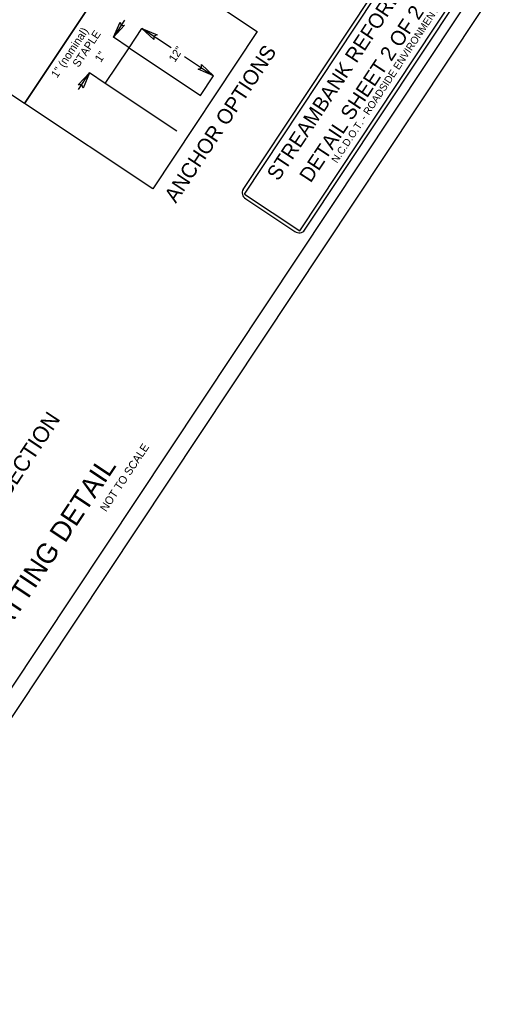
# Model space of a CAD drawing. Extents: x 561231 to 564240, y 590260 to 602519.
# Drawn here: x 563838 to 564240, y 590260 to 591058 of the extents above; entities that cross this region are included whole.
import ezdxf

# ---------------------------------------------------------------- set-up
doc = ezdxf.new("R2010")
doc.units = 0
doc.layers.add('Old_Level_1', color=7, linetype='Continuous')
doc.layers.add('Sheet Plot Border Outside CELL', color=7, linetype='Continuous')

msp = doc.modelspace()

# ---------------------------------------------------------------- linework, layer by layer
at = {"layer": 'Old_Level_1'}
for p, q in [((564021.45, 590918.69), (564158.67, 591125.58)), ((564022.5, 590914.8), (564162.65, 591126.13)), ((564067.77, 590884.76), (564207.92, 591096.09)), ((564071.76, 590885.31), (564208.97, 591092.21)), ((563924.5, 591057.12), (563915.26, 591043.22)), ((563928.1, 591034.49), (563938.64, 591050.47)), ((563936.85, 591047.77), (563936.82, 591047.73)), ((563962.45, 591034.64), (563938.64, 591050.46)), ((563912.53, 591045.03), (563912.53, 591045.03)), ((563928.1, 591034.49), (563915.26, 591043.22)), ((563973.37, 591027.38), (563997.18, 591011.56)), ((563886.76, 591000.32), (563895.82, 591013.96)), ((563908.64, 591005.23), (563895.81, 591013.97)), ((563898.54, 591012.16), (563898.55, 591012.15)), ((563986.62, 590995.57), (563997.18, 591011.56)), ((563995.37, 591008.83), (563995.37, 591008.83)), ((564022.5, 590914.8), (564067.77, 590884.76)), ((564023.55, 590910.92), (564063.79, 590884.22))]:
    msp.add_line(p, q, dxfattribs=at)
for points in [[(563698.59, 591448.69), (563200.53, 590699.06), (563725.27, 590350.42), (564223.33, 591100.04)], [(563700.37, 591083.36), (563785.96, 591212.17), (563928.11, 591117.72), (563842.52, 590988.91)], [(563842.52, 590988.91), (563928.11, 591117.72), (564033.01, 591048.02), (563947.43, 590919.21)], [(563924.5, 591053.01), (563915.26, 591043.22), (563920.69, 591055.64), (563921.71, 591052.92)], [(563948.42, 591041.22), (563938.64, 591050.46), (563951.06, 591045.04), (563948.33, 591044.02)], [(563886.58, 591004.17), (563895.82, 591013.96), (563890.41, 591001.55), (563889.38, 591004.26)], [(563987.39, 591020.8), (563997.18, 591011.56), (563984.76, 591016.98), (563987.48, 591018)]]:
    msp.add_lwpolyline(points, close=True, dxfattribs=at)
msp.add_lwpolyline([(563967.17, 590966.32), (563908.64, 591005.23), (563928.1, 591034.49), (563986.62, 590995.57)], dxfattribs=at)
for centre, major_axis, start_param, end_param in [((564026.48, 590915.35), (-5.03, 3.34), 0.000749, 1.571546), ((564066.73, 590888.65), (5.03, -3.34), 4.713138, 6.283935)]:
    msp.add_ellipse(centre, major_axis=major_axis, ratio=0.880425, start_param=start_param, end_param=end_param, dxfattribs=at)
at = {"layer": 'Sheet Plot Border Outside CELL'}
msp.add_lwpolyline([(563681.23, 590259.74), (564240.22, 591101.07), (563692.99, 591464.65), (563134, 590623.32)], close=True, dxfattribs=at)

# ---------------------------------------------------------------- texts
at = {"layer": 'Old_Level_1'}
for s, height, rotation, p in [('STREAMBANK REFORESTATION', 12.0731, 56.44825, (564050.12, 590924.87)), ('N.C.D.O.T. - ROADSIDE ENVIRONMENTAL UNIT', 6.0369, 56.44825, (564098.29, 590939.69)), ('   DETAIL SHEET 2 OF 2', 12.0731, 56.44825, (564069.23, 590912.19)), ('1" (nominal)', 6.5511, 56.38031, (563869.18, 591009.33)), ('STAPLE', 6.551, 56.38031, (563886.77, 591018.05)), ('1"', 6.551, 56.38031, (563905, 591022.15)), ('ANCHOR OPTIONS', 12.2832, 56.39933, (563966.38, 590906.77)), ('12"', 6.551, 56.38031, (563965.56, 591022.23)), ('TYPICAL CROSS SECTION', 13.102, 56.39933, (563749.01, 590545.12)), ('NOT TO SCALE', 6.5511, 56.39933, (563909.3, 590654.35)), ('COIR FIBER MATTING DETAIL', 16.3776, 56.39933, (563745.07, 590431.91))]:
    msp.add_text(s, height=height, rotation=rotation, dxfattribs=at).set_placement(p)

doc.saveas('drawing.dxf')
